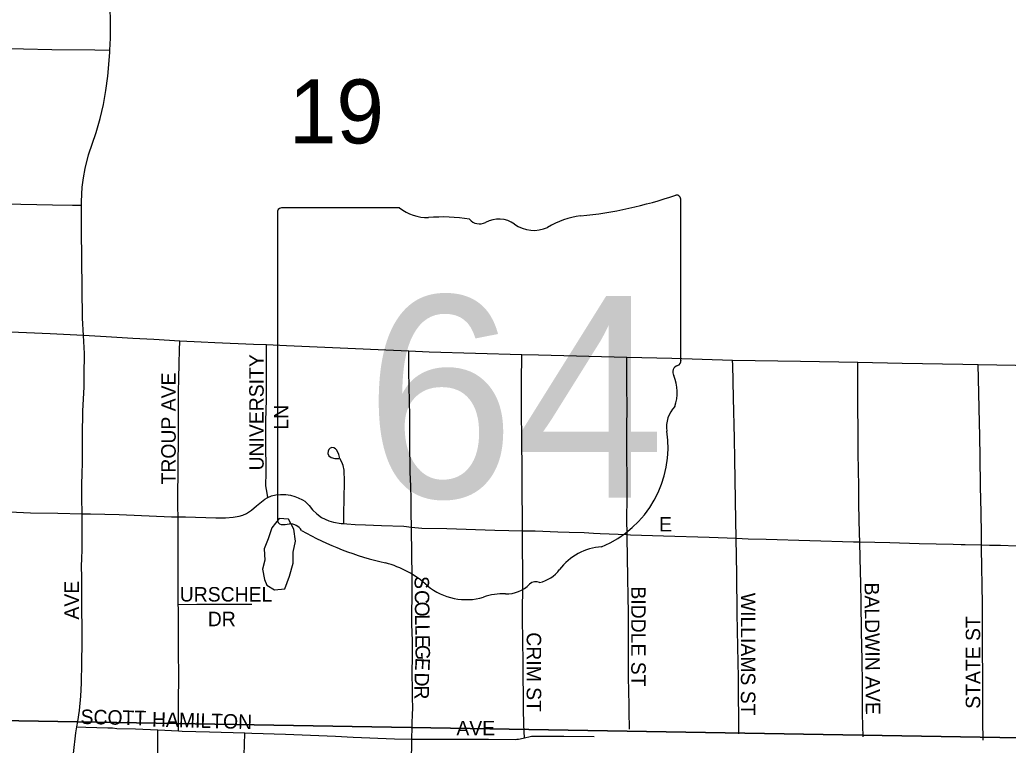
# Model space of a CAD drawing. Extents: x 1443599 to 1910620, y 1028088 to 1361369.
# Drawn here: x 1654352 to 1657763, y 1229992 to 1232496 of the extents above; entities that cross this region are included whole.
import ezdxf

# ---------------------------------------------------------------- set-up
doc = ezdxf.new("R2010")
doc.units = 0
for name, color, linetype in [('GM_X_City_Street', 7, 'Continuous'), ('GM_X_City_Street_Text', 7, 'Continuous'), ('GM_X_Minor_Lake', 7, 'Continuous'), ('GM_X_Section', 7, 'Continuous'), ('GM_X_Section_Text', 7, 'Continuous'), ('GM_X_State_Location', 7, 'Continuous'), ('GM_X_State_Route', 7, 'Continuous'), ('GM_X_State_Shield', 7, 'Continuous')]:
    doc.layers.add(name, color=color, linetype=linetype)

msp = doc.modelspace()

# ---------------------------------------------------------------- linework, layer by layer
at = {"layer": 'GM_X_City_Street'}
for points in [[(1654662.8, 1232391.2), (1654664.6, 1232432.6), (1654663.4, 1232596.9), (1654659.6, 1232699.3)], [(1653782.1, 1232402.6), (1653798.2, 1232402.6), (1653813.9, 1232402.6), (1653829.5, 1232402.8), (1653846, 1232402.3), (1653911.1, 1232401.4), (1653960.3, 1232400.6), (1654203.6, 1232396.7), (1654365.3, 1232395.6), (1654462.9, 1232394.2), (1654611.1, 1232392), (1654662.8, 1232391.2)], [(1654564.7, 1231855.8), (1654564.7, 1231869.5), (1654567.5, 1231918.3), (1654571.4, 1231950.6), (1654577.4, 1231982.5), (1654589.7, 1232029.8), (1654615.1, 1232107.7), (1654628.9, 1232155.2), (1654640.5, 1232203.4), (1654649.3, 1232252.1), (1654655.6, 1232301.1), (1654662.5, 1232383.2), (1654662.8, 1232391.2)], [(1653775.6, 1231869.2), (1653999.9, 1231867.2), (1654144.9, 1231864.1), (1654302.1, 1231860.8), (1654465.4, 1231857.3), (1654534.1, 1231856.3), (1654564.7, 1231855.8)], [(1654571.5, 1231405.9), (1654568.3, 1231466.3), (1654564.8, 1231771.2), (1654564.7, 1231855.8)], [(1654566.8, 1230791), (1654566.4, 1230846.5), (1654566.4, 1230885.7), (1654567.3, 1230935.6), (1654568.1, 1230961.6), (1654568.1, 1230998.6), (1654568.5, 1231033.7), (1654568.6, 1231082.2), (1654569.2, 1231124.1), (1654570.1, 1231146.6), (1654573.7, 1231228.3), (1654574.1, 1231269.6), (1654575.1, 1231344.7), (1654571.5, 1231405.9)], [(1654898.2, 1230780.4), (1654897.8, 1230815.2), (1654897.6, 1230865.5), (1654898.2, 1230926.2), (1654898.7, 1230974.6), (1654899.2, 1231030.9), (1654899.5, 1231071.9), (1654899.8, 1231123.9), (1654900.1, 1231166.1), (1654900.3, 1231211.9), (1654901.3, 1231258.1), (1654902.6, 1231309.2), (1654903.7, 1231356.1), (1654904.4, 1231387.1)], [(1655208.4, 1230846.9), (1655205.3, 1230861.5), (1655201.5, 1230887.1), (1655202, 1230933), (1655201.8, 1230968.9), (1655201.7, 1231005.3), (1655201.5, 1231055.2), (1655201.2, 1231110.7), (1655203.5, 1231185.8), (1655203.3, 1231237.9), (1655204, 1231290.1), (1655203.2, 1231332.6), (1655203.3, 1231342.6), (1655203.6, 1231373.7)], [(1655703.8, 1230745.2), (1655703, 1230793.8), (1655702.9, 1230842.9), (1655701.7, 1230885.7), (1655699.8, 1230934.8), (1655697.7, 1231039.8), (1655698.4, 1231128.8), (1655696.4, 1231230.4), (1655694.4, 1231280.5), (1655694.4, 1231321.6), (1655694.4, 1231352.3)], [(1656087.3, 1230732), (1656087.1, 1230763.5), (1656086.3, 1230877.2), (1656085.7, 1230962.9), (1656084.8, 1231024), (1656083.2, 1231167), (1656083.8, 1231261.9), (1656084.2, 1231324.4), (1656084.4, 1231340.1)], [(1656447.9, 1230719), (1656446.9, 1230771.2), (1656448.5, 1230847.6), (1656448.1, 1230914.3), (1656446.8, 1230992.5), (1656447.1, 1231045.9), (1656447.5, 1231095), (1656447.9, 1231151.2), (1656447.2, 1231238), (1656446.7, 1231304.6), (1656446.5, 1231330.5)], [(1656824.3, 1230706.2), (1656823.3, 1230767.5), (1656821, 1230909.5), (1656820.1, 1230979), (1656819.2, 1231050.4), (1656815.5, 1231190.9), (1656812.5, 1231305.6), (1656812.1, 1231320.6)], [(1657251, 1230694.2), (1657250.3, 1230722.8), (1657248.1, 1230822.9), (1657247.2, 1230887.3), (1657246.4, 1230940.6), (1657245.5, 1231002.2), (1657245.2, 1231081), (1657244.8, 1231157.9), (1657244.5, 1231235.4), (1657244.2, 1231287.3), (1657244.1, 1231312.6)], [(1657670.8, 1230683.5), (1657670.9, 1230720.1), (1657670.1, 1230795.6), (1657668.2, 1230885.5), (1657666.7, 1230987.6), (1657665.6, 1231058.2), (1657663.2, 1231155.4), (1657660.7, 1231258.2), (1657659.6, 1231304.8)], [(1655470.4, 1230756.8), (1655470.8, 1230779.2), (1655472, 1230854.7), (1655472.9, 1230889.7), (1655472.8, 1230902.3), (1655471.4, 1230941.5), (1655468.6, 1230957.8), (1655463.8, 1230968.7), (1655456.5, 1230981.3), (1655453.3, 1230996), (1655445.9, 1231010.7), (1655441.5, 1231015.4), (1655435.7, 1231018.3), (1655429.3, 1231019.2), (1655426.1, 1231018.7), (1655423.2, 1231017.5), (1655420.9, 1231015.6), (1655418.9, 1231013.3), (1655416.2, 1231007.5), (1655415.7, 1230999.1), (1655418.7, 1230990.8), (1655426.5, 1230984.8), (1655439.1, 1230982.2), (1655453.4, 1230981.3)], [(1654898.2, 1230780.4), (1654924.2, 1230779.9), (1655029.1, 1230776.4), (1655062.3, 1230776.5), (1655088.8, 1230778.9), (1655108.7, 1230782.3), (1655121.9, 1230786.1), (1655134.5, 1230791.9), (1655151.4, 1230803.1), (1655169.4, 1230818.1), (1655186.6, 1230832.6), (1655191.8, 1230836.5), (1655198.2, 1230841.3), (1655206.2, 1230845.9), (1655208.4, 1230846.9)], [(1655208.4, 1230846.9), (1655220.6, 1230852.3), (1655235.7, 1230856.1), (1655251.4, 1230857.5), (1655270.6, 1230857.2), (1655286.2, 1230855.1), (1655301.2, 1230850.9), (1655312.5, 1230845.8), (1655327.5, 1230838.7), (1655335.3, 1230834.4), (1655341.9, 1230829.2), (1655350.3, 1230819.7), (1655362.2, 1230805.1), (1655377.2, 1230790.7), (1655393.5, 1230778.4), (1655405.5, 1230771.9), (1655418.2, 1230766.9), (1655434.5, 1230762.4), (1655460.7, 1230757.9), (1655470.4, 1230756.8)], [(1654266.3, 1230799.8), (1654389.4, 1230794.7), (1654482.8, 1230792.6), (1654566.8, 1230791)], [(1654549, 1230055.2), (1654551.8, 1230073.5), (1654558.2, 1230112.1), (1654563.1, 1230160.7), (1654565.4, 1230206.3), (1654566.3, 1230277.6), (1654567.1, 1230345.9), (1654566.9, 1230391.6), (1654566.6, 1230466.7), (1654566.6, 1230489.5), (1654566.3, 1230528.6), (1654566.2, 1230570.5), (1654565.4, 1230611.4), (1654565.9, 1230635.7), (1654567.2, 1230667.1), (1654567.3, 1230693), (1654567, 1230745), (1654566.9, 1230774.3), (1654566.8, 1230791)], [(1654566.8, 1230791), (1654595.7, 1230790.5), (1654694.9, 1230788.6), (1654875.1, 1230780.9), (1654898.2, 1230780.4)], [(1654899.1, 1230477.9), (1654898.9, 1230521.5), (1654898.7, 1230564.1), (1654898.6, 1230611), (1654898.4, 1230647), (1654899.1, 1230712.5), (1654898.7, 1230744.7), (1654898.2, 1230780.4)], [(1655470.4, 1230756.8), (1655480.2, 1230755.7), (1655509.8, 1230753.9), (1655545.3, 1230752.3), (1655600.5, 1230750.3), (1655677.5, 1230747.9), (1655703.8, 1230745.2)], [(1655703.8, 1230745.2), (1655739.2, 1230741.4), (1655826.1, 1230739.7), (1655991.5, 1230734.2), (1656039.3, 1230732.9), (1656087.3, 1230732)], [(1655705.6, 1230012.6), (1655706.4, 1230053.9), (1655706.4, 1230066.8), (1655707.7, 1230099.4), (1655708.2, 1230119), (1655708.2, 1230129), (1655707.9, 1230147.9), (1655707.7, 1230177.5), (1655706.7, 1230246.3), (1655706.7, 1230259.1), (1655707.2, 1230280.6), (1655707.2, 1230308), (1655707, 1230347.2), (1655706.6, 1230386), (1655705.6, 1230405.5), (1655705.6, 1230457.5), (1655706.5, 1230496.9), (1655706, 1230536.4), (1655705.9, 1230552.6), (1655705.8, 1230565.5), (1655706.1, 1230581.6), (1655706.3, 1230601.2), (1655705.6, 1230627.5), (1655704.9, 1230653.1), (1655704.8, 1230675.9), (1655704.6, 1230682.5), (1655704.4, 1230708.7), (1655703.8, 1230745.2)], [(1656093.5, 1230017), (1656092, 1230062.5), (1656091, 1230118.7), (1656090.1, 1230176.2), (1656089.4, 1230216.1), (1656089.1, 1230286.4), (1656088.1, 1230344.8), (1656086.5, 1230439.1), (1656087.9, 1230554.6), (1656087.5, 1230712.3), (1656087.3, 1230732)], [(1656087.3, 1230732), (1656104.9, 1230731.6), (1656130.5, 1230732.1), (1656208.5, 1230728.7), (1656247.6, 1230727.5), (1656299.7, 1230725.8), (1656332.1, 1230724.1), (1656354.5, 1230722.8), (1656447.9, 1230719)], [(1656456, 1230046.8), (1656455.1, 1230109.3), (1656454.6, 1230136.6), (1656454.1, 1230171.8), (1656453.1, 1230233.7), (1656453.2, 1230271.4), (1656453.2, 1230345.1), (1656453, 1230388.6), (1656452.6, 1230449.5), (1656451.6, 1230504.8), (1656450.6, 1230569.4), (1656449.4, 1230642.2), (1656448.1, 1230707.7), (1656447.9, 1230719)], [(1656447.9, 1230719), (1656459.3, 1230718.6), (1656574.1, 1230714.7), (1656731.5, 1230709.7), (1656824.3, 1230706.2)], [(1656833.1, 1230031.7), (1656833.1, 1230089.6), (1656833, 1230160.4), (1656832, 1230226), (1656830.3, 1230332), (1656828.4, 1230447), (1656826.3, 1230580.8), (1656824.3, 1230706.2)], [(1656824.3, 1230706.2), (1656865.8, 1230704.7), (1656928.2, 1230703.6), (1657078.9, 1230699.2), (1657229.8, 1230694.6), (1657251, 1230694.2)], [(1657263.1, 1230020.9), (1657260.9, 1230098.7), (1657260.6, 1230205.5), (1657259.1, 1230285.8), (1657257.3, 1230384.4), (1657255.6, 1230484.4), (1657254.1, 1230549.2), (1657252.2, 1230638.2), (1657251, 1230694.2)], [(1657251, 1230694.2), (1657354.5, 1230692), (1657456.1, 1230688.8), (1657515, 1230687), (1657573.3, 1230686.2), (1657601.3, 1230685.3), (1657614.4, 1230685.1), (1657670.8, 1230683.5)], [(1657677.3, 1230009.4), (1657676.2, 1230074.7), (1657675.5, 1230207.8), (1657674.8, 1230344.6), (1657674.3, 1230425.6), (1657674, 1230480), (1657670.7, 1230670.9), (1657670.8, 1230683.5)], [(1657670.8, 1230683.5), (1657698.7, 1230682.7), (1657737.2, 1230682.1), (1657790.8, 1230680.5), (1657806.5, 1230679.9), (1657855.5, 1230677.7), (1657892.1, 1230675.8), (1657914.7, 1230674.7), (1658019.5, 1230669.6), (1658104.9, 1230667.7), (1658173.8, 1230667.4), (1658334.6, 1230665.1), (1658352.7, 1230664.9)], [(1654899.1, 1230477.9), (1654963.2, 1230478.5), (1655008.1, 1230478.9), (1655053.1, 1230478.7), (1655093.9, 1230478.4), (1655153.3, 1230478.3)], [(1654899.3, 1230041.6), (1654899.5, 1230062.8), (1654900, 1230133.7), (1654900.4, 1230238.8), (1654899.6, 1230307.9), (1654900.3, 1230370.3), (1654899.8, 1230462.3), (1654899.1, 1230477.9)], [(1654526.3, 1229765.3), (1654526.3, 1229766.6), (1654530, 1229858.5), (1654534.2, 1229923.9), (1654537.4, 1229962.8), (1654545.7, 1230034.5), (1654549, 1230055.2)], [(1654549, 1230055.2), (1654580.2, 1230054.2), (1654656.4, 1230051.7), (1654671.9, 1230051.6), (1654687.5, 1230050.2), (1654751.9, 1230048.3), (1654828.2, 1230044.8)], [(1654821.8, 1229754.2), (1654827.1, 1229878.7), (1654827.3, 1229907), (1654828, 1230011.6), (1654828.2, 1230044.8)], [(1654828.2, 1230044.8), (1654899.3, 1230041.6)], [(1654899.3, 1230041.6), (1654912, 1230041), (1655006.5, 1230038.6), (1655129, 1230034.4)], [(1655116.2, 1229744.6), (1655118.8, 1229804.7), (1655124, 1229917), (1655126.5, 1229958.8), (1655127.9, 1229992.8), (1655129, 1230034.4)], [(1655129, 1230034.4), (1655153.4, 1230033.6), (1655268.6, 1230029.7), (1655441.9, 1230022.9), (1655502.4, 1230019.7), (1655645.1, 1230014), (1655705.6, 1230012.6)], [(1656093.5, 1230017), (1656113.3, 1230022), (1656117.7, 1230022.7), (1656120.7, 1230023), (1656128.3, 1230023.3), (1656229.6, 1230022.8), (1656334.2, 1230022.2)], [(1655699.1, 1229725.6), (1655700.2, 1229755.5), (1655701.1, 1229788.1), (1655701.3, 1229801.2), (1655702.3, 1229873.3), (1655704.1, 1229929.1), (1655705.6, 1230012.6)], [(1655705.6, 1230012.6), (1655710, 1230012.5), (1655838.3, 1230013.3), (1655969.1, 1230012.5), (1656061.1, 1230011.7), (1656067, 1230012.3), (1656073.6, 1230013), (1656078.7, 1230013.8), (1656093.5, 1230017)]]:
    msp.add_lwpolyline(points, dxfattribs=at)
at = {"layer": 'GM_X_Minor_Lake'}
msp.add_line((1655195.3, 1230670.3), (1655197.2, 1230630.2), dxfattribs=at)
msp.add_lwpolyline([(1655197.2, 1230630.2), (1655189.1, 1230600.2), (1655197, 1230564), (1655204.9, 1230543.9), (1655230.9, 1230527.8), (1655267, 1230531.7), (1655283.1, 1230575.8), (1655295.3, 1230619.9), (1655295.4, 1230642), (1655295.4, 1230658), (1655303.5, 1230696.1), (1655297.7, 1230738.2), (1655279.7, 1230772.4), (1655247.7, 1230774.5), (1655221.5, 1230742.5), (1655209.4, 1230704.4), (1655195.3, 1230670.3)], dxfattribs=at)
at = {"layer": 'GM_X_Section'}
for points in [[(1652604.1, 1235400.9), (1658278.7, 1235264.2), (1658343.9, 1230008.1), (1652586.7, 1230105.6), (1652586.1, 1230207.6)], [(1652586.7, 1230105.6), (1658343.9, 1230008.1), (1658121.8, 1224660.7), (1652515.7, 1224828.2), (1652508.6, 1224902.3)]]:
    msp.add_lwpolyline(points, close=True, dxfattribs=at)
at = {"layer": 'GM_X_State_Route'}
for points in [[(1655025.2, 1231381.6), (1654977.8, 1231383.7), (1654904.4, 1231387.1), (1654814.7, 1231392.2), (1654742.2, 1231396.3), (1654650.4, 1231401.4), (1654571.5, 1231405.9), (1654456.8, 1231411.7), (1654264.5, 1231420.3), (1654248.7, 1231421.2)], [(1657607, 1231305.8), (1657396.9, 1231309.7), (1657244.1, 1231312.6), (1657045.9, 1231316.3), (1656812.1, 1231320.6), (1656602, 1231326.4), (1656446.5, 1231330.5), (1656142.3, 1231338.4), (1656084.4, 1231340.1), (1655765, 1231349.2), (1655694.4, 1231352.3), (1655404.3, 1231365), (1655273, 1231370.8), (1655203.6, 1231373.7), (1655158.2, 1231375.6), (1655025.2, 1231381.6)], [(1660965.8, 1231240), (1660929.5, 1231241.4), (1660897.7, 1231242.6), (1660817.9, 1231244.1), (1660686.6, 1231246.7), (1660267.8, 1231255.5), (1660110.6, 1231258.4), (1659959.9, 1231260.8), (1659806.2, 1231264.1), (1659600.7, 1231269.5), (1659399.5, 1231271.6), (1659139, 1231278.1), (1658879.7, 1231282.4), (1658581.8, 1231288.8), (1658445.5, 1231291), (1658347.3, 1231292.7), (1658260, 1231293.5), (1658029.4, 1231297.9), (1657787.9, 1231302.4), (1657659.6, 1231304.8), (1657607, 1231305.8)]]:
    msp.add_lwpolyline(points, dxfattribs=at)
at = {"layer": 'GM_X_State_Shield'}
for p, q in [((1656633.2, 1231320.6), (1656633.2, 1231873.3)), ((1655662.5, 1231847.1), (1655254.8, 1231847.1)), ((1655241.1, 1231828.9), (1655241.1, 1230772.3)), ((1656633.1, 1231320.7), (1656633.2, 1231320.6))]:
    msp.add_line(p, q, dxfattribs=at)
for centre, radius, start, end in [((1656137.3, 1233287.7), 1476.4, 275.8445, 288.9065), ((1656617.8, 1231875.6), 15.5, 351.8621, 97.738), ((1655257, 1231831.2), 16.1, 98.1301, 188.1301), ((1655759.6, 1231969.8), 156.4, 231.6195, 271.1119), ((1655811.4, 1231253.9), 561.6, 80.4867, 94.9883), ((1655938.9, 1231836.7), 45.1, 219.7921, 297.1024), ((1656005.2, 1231714.5), 93.8, 54.4667, 119.1411), ((1656325.6, 1231524.4), 297, 97.3462, 120.7689), ((1656126.3, 1231882), 112.9, 233.8562, 294.8282), ((1656616.7, 1231318.4), 16.6, 289.6038, 7.7341), ((1656629.6, 1231280), 24, 107.944, 210.337), ((1656477, 1231210.1), 144, 340.033, 23.6496), ((1656688.7, 1231089.2), 104.8, 136.8065, 186.9296), ((1656220, 1231018.9), 369.3, 292.3089, 8.9858), ((1655257.1, 1230770), 16.3, 171.9584, 258.3066), ((1655259.6, 1230878.1), 124.2, 267.339, 280.6039), ((1655285, 1230711.3), 44.8, 29.7484, 93.2717), ((1655850.3, 1231660.7), 1066.1, 240.4129, 257.1985), ((1656375.7, 1230475.7), 202.2, 94.4031, 142.5768), ((1655532.4, 1230297.6), 333.6, 47.1842, 75.836), ((1656119.5, 1230669.9), 119.3, 282.8732, 323.2771), ((1655893.2, 1230706.1), 211.7, 230.7004, 286.2918), ((1656031, 1230627), 112.8, 268.777, 315.5493), ((1656133, 1230524.6), 31.8, 65.7517, 132.6484), ((1656015.5, 1230340.8), 173.9, 85.6951, 111.2099)]:
    msp.add_arc(centre, radius, start, end, dxfattribs=at)

# ---------------------------------------------------------------- texts
at = {"layer": 'GM_X_City_Street_Text'}
for s, rotation, p in [('UNIVERSITY', 90, (1655193.8, 1230940.5)), ('TROUP AVE', 90, (1654890.2, 1230892.1)), ('LN', 90, (1655278.9, 1231081.3)), ('E', 0, (1656558.4, 1230729.9)), ('S', 270.765, (1655714.2, 1230575.5)), ('AVE', 90, (1654555.8, 1230425.7)), ('URSCHEL', 0, (1654904, 1230487.9)), ('BIDDLE ST', 270, (1656462.2, 1230540.1)), ('BALDWIN AVE', 270.5803, (1657267.4, 1230553.5)), ('C', 270.7658, (1655714.9, 1230527.1)), ('WILLIAMS ST', 270, (1656840.6, 1230518.1)), ('O', 270.7587, (1655715.4, 1230487.5)), ('DR', 0, (1655000.8, 1230402.8)), ('L', 270.765, (1655716, 1230443.5)), ('STATE ST', 90, (1657666.6, 1230117.7)), ('L', 270.7616, (1655716.5, 1230408.3)), ('E', 270.7616, (1655717, 1230373.1)), ('CRIM ST', 270, (1656101.4, 1230381.7)), ('G', 270.7704, (1655717.4, 1230337.9)), ('E', 267.0748, (1655718.1, 1230294.8)), ('D', 269.0019, (1655715, 1230243.3)), ('R', 270.0178, (1655714.2, 1230198.3)), ('SCOTT', 358.7276, (1654561.3, 1230065.5)), ('HAMILTON', 358.4504, (1654807.8, 1230056.7)), ('AVE', 0, (1655858.8, 1230025.9))]:
    msp.add_text(s, height=50, rotation=rotation, dxfattribs=at).set_placement(p)
at = {"layer": 'GM_X_Section_Text'}
msp.add_text('19', height=221, rotation=0, dxfattribs=at).set_placement((1655280.2, 1232069.4))
at = {"layer": 'GM_X_State_Location'}
for s in ['r', 's']:
    msp.add_text(s, height=1, dxfattribs=at).set_placement((1655921.4, 1231230.4))
msp.add_text('64', height=1, rotation=0, dxfattribs=at).set_placement((1655669.6, 1231157.6))
at = {"layer": 'GM_X_State_Shield'}
msp.add_text('64', height=696.1, dxfattribs=at).set_placement((1655543.6, 1230846.8))

doc.saveas('drawing.dxf')
